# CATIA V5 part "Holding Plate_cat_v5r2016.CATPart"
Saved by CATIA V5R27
Part number: Holding Plate
Bounding box of the stored display mesh (mm): x -16 to 16, y -16 to 16, z 0 to 7
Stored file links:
  E:\_Deepak\2017_Deepak\CATIA\Resources\Tutorial Files\Tutorials\c13_catia_v5_6r2016_tut\c13tut2\c13tut02.CATParts\Holding Plate_cat_v5r2016.CATPart
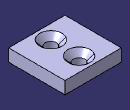
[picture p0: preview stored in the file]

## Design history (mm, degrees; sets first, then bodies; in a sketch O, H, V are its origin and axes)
Body1 (main body)
  Sketch1 on xy-plane, origin (0, 0, 0), H (1, 0, 0), V (0, 1, 0)
    line L1 (-16, 16) -> (16, 16)
    line L2 (16, 16) -> (16, -16)
    line L3 (16, -16) -> (-16, -16)
    line L4 (-16, -16) -> (-16, 16)
    construction line L5 (-16, 16) -> (16, -16)
    length L2 = 32
    length L3 = 32
    distance H L3 = 16
    distance V L4 = 16
    horizontal: L1 H, L3 H
    vertical: L2 V, L4 V
  Pad1: profile Sketch1, direction (0, 0, 1), length 7
  Sketch2 on face of Pad1, origin (-0.9262, 8.6399, 7), H (1, 0, 0), V (0, 1, 0)
    point P1 (0.9262, -0.6399)
    reference intersected line E1 through (0.9262, 0) direction (0, 1) from yz-plane
    reference projected line E3 (-15.0738, 7.3601) -> (16.9262, 7.3601) from edge of Pad1
    distance P1 E3 = 8
    coincidence: E1 P1
  Hole1: placed by Sketch2, at (0, 8, 7) direction (0, 0, -1), diameter 6.4, depth 10, countersink depth 5, countersink angle 90
  Mirror1: of Hole1, about zx-plane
